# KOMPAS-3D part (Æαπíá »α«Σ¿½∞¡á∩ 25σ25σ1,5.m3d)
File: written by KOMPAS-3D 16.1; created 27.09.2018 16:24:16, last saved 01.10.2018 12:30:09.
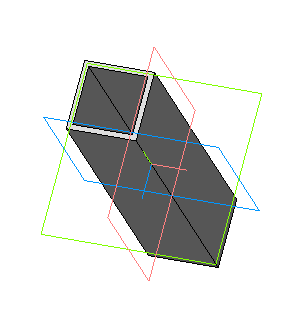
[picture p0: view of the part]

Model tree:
1. Эскиз:1
2. Операция выдавливания:1  (labels: Труба профильная 25х25х1,5)
     Расстояние 2 = 10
